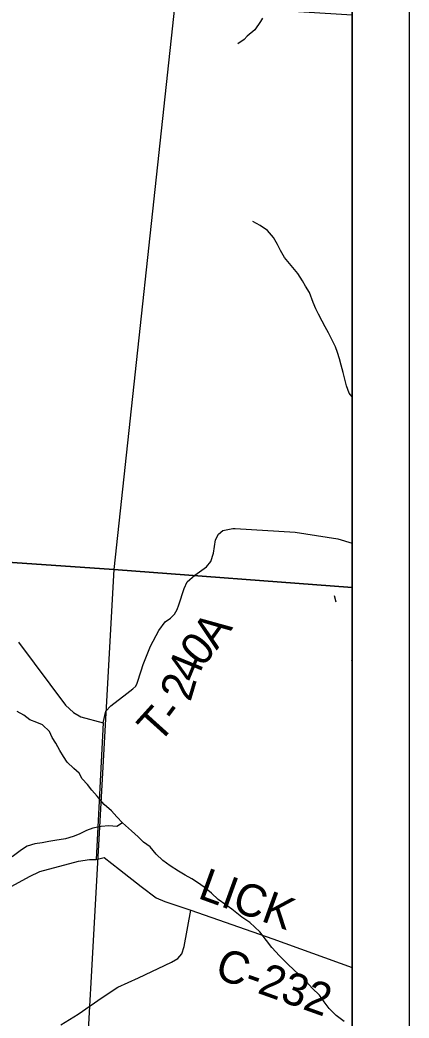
# Model space of a CAD drawing. Extents: x 0 to 34, y 0 to 22.
# Drawn here: x 8.316 to 9, y 15.475 to 17.231 of the extents above; entities that cross this region are included whole.
import ezdxf

# ---------------------------------------------------------------- set-up
doc = ezdxf.new("R2010")
doc.units = 0
for name, color, linetype in [('GM_X_Corporation', 7, 'Continuous'), ('GM_X_County_Road', 7, 'Continuous'), ('GM_X_County_Road_Text', 7, 'Continuous'), ('GM_X_Minor_River', 7, 'Continuous'), ('GM_X_Township_Road', 7, 'Continuous'), ('GM_X_Township_Road_Text', 7, 'Continuous'), ('SH_Data', 7, 'Continuous')]:
    doc.layers.add(name, color=color, linetype=linetype)

msp = doc.modelspace()

# ---------------------------------------------------------------- linework, layer by layer
at = {"layer": 'GM_X_Corporation'}
for p, q in [((8.9, 17.018), (8.9, 18.0245)), ((8.9, 14.1), (8.9, 18.0235)), ((8.9, 16.0103), (8.9, 17.018)), ((8.9, 15.0158), (8.9, 16.0103))]:
    msp.add_line(p, q, dxfattribs=at)
msp.add_lwpolyline([(8.9, 14.1), (8.9, 18.2459)], dxfattribs=at)
for points in [[(7.5885, 17.3345), (8.5882, 17.2585), (8.4813, 16.2644), (7.4964, 16.3324)], [(8.9, 16.2326), (8.9, 17.2392), (8.5882, 17.2585), (8.4813, 16.2644)], [(7.4964, 16.3324), (8.4813, 16.2644), (8.4262, 15.2749), (7.434, 15.3319)], [(8.9, 15.2382), (8.9, 16.2326), (8.4813, 16.2644), (8.4262, 15.2749)]]:
    msp.add_lwpolyline(points, close=True, dxfattribs=at)
at = {"layer": 'GM_X_County_Road'}
for points in [[(8.388, 15.4633), (8.4184, 15.4821), (8.4607, 15.5114), (8.4885, 15.5297), (8.5245, 15.5459), (8.5826, 15.5734), (8.5936, 15.5799), (8.6009, 15.5883), (8.6051, 15.6014), (8.6166, 15.6649)], [(8.6166, 15.6649), (8.7604, 15.6147), (8.9, 15.5645)]]:
    msp.add_lwpolyline(points, dxfattribs=at)
at = {"layer": 'GM_X_Minor_River'}
for p, q in [((8.8717, 16.2065), (8.8691, 16.2179)), ((8.9, 16.1042), (8.8991, 16.1045))]:
    msp.add_line(p, q, dxfattribs=at)
for points in [[(8.7426, 17.2339), (8.7392, 17.2283), (8.7288, 17.2131), (8.7155, 17.2022), (8.7101, 17.1965), (8.6991, 17.1886)], [(8.9, 16.5678), (8.895, 16.5745), (8.8902, 16.587), (8.8868, 16.6011), (8.8842, 16.6109), (8.8808, 16.6238), (8.8778, 16.6345), (8.8744, 16.6458), (8.8706, 16.6557), (8.8582, 16.6807), (8.8529, 16.691), (8.8473, 16.7012), (8.8409, 16.713), (8.836, 16.7229), (8.8315, 16.7339), (8.8251, 16.7513), (8.8183, 16.7623), (8.813, 16.7718), (8.8047, 16.7851), (8.7926, 16.7988), (8.7813, 16.8128), (8.7741, 16.8253), (8.7689, 16.836), (8.7617, 16.8481), (8.7515, 16.8606), (8.7383, 16.8694), (8.7254, 16.8762)], [(8.8858, 15.4691), (8.8718, 15.4801), (8.8594, 15.4923), (8.8511, 15.5037), (8.8428, 15.5155), (8.83, 15.5281), (8.8149, 15.5441), (8.7987, 15.5589), (8.7859, 15.5715), (8.7723, 15.5845), (8.7588, 15.5993), (8.7497, 15.6119), (8.7381, 15.6267), (8.72, 15.6431), (8.706, 15.653), (8.6886, 15.6671), (8.6781, 15.6744), (8.6648, 15.6839), (8.6528, 15.6949), (8.64, 15.7056), (8.6282, 15.7136), (8.6184, 15.7201), (8.6067, 15.7266), (8.595, 15.7335), (8.5803, 15.743), (8.5675, 15.7522), (8.5554, 15.7636), (8.5448, 15.7762), (8.5335, 15.7846), (8.5241, 15.7941), (8.512, 15.8044), (8.4966, 15.8188), (8.4864, 15.8295), (8.4773, 15.8398), (8.4641, 15.8508), (8.4517, 15.8653), (8.4423, 15.876), (8.4348, 15.8859), (8.4253, 15.8958), (8.4205, 15.906), (8.4107, 15.914), (8.399, 15.9254), (8.393, 15.9353), (8.3866, 15.946), (8.3794, 15.9585), (8.3731, 15.9688), (8.3682, 15.9794), (8.3557, 15.9909), (8.3459, 15.9951), (8.3338, 15.9997), (8.3232, 16.0081), (8.3112, 16.0146)], [(8.4966, 15.8188), (8.4863, 15.8124), (8.4723, 15.8136), (8.459, 15.8125), (8.4446, 15.8092), (8.4329, 15.8054), (8.4203, 15.799), (8.4097, 15.7945), (8.396, 15.7904), (8.3775, 15.7878), (8.3672, 15.7856), (8.3555, 15.7837), (8.3426, 15.7819), (8.3289, 15.7774), (8.3191, 15.7709), (8.3023, 15.7589)]]:
    msp.add_lwpolyline(points, dxfattribs=at)
at = {"layer": 'GM_X_Township_Road'}
for points in [[(8.5292, 16.086), (8.5328, 16.0972), (8.5454, 16.1294), (8.5602, 16.1571), (8.5713, 16.1719), (8.5808, 16.1787), (8.588, 16.1855), (8.5926, 16.1939), (8.5952, 16.2022), (8.6048, 16.231), (8.6101, 16.2424), (8.6238, 16.2542), (8.6439, 16.2689), (8.6515, 16.278), (8.6561, 16.2928), (8.66, 16.3163), (8.665, 16.3266), (8.6726, 16.3326), (8.6904, 16.3364), (8.6943, 16.3362)], [(8.6943, 16.3362), (8.7999, 16.33), (8.8749, 16.3184), (8.9, 16.3104)], [(8.3138, 16.1365), (8.369, 16.0623), (8.3965, 16.0258), (8.4101, 16.0128), (8.4234, 16.0052), (8.4626, 15.9947), (8.4504, 15.7542)], [(8.4626, 15.9947), (8.467, 16.0153), (8.4761, 16.0244), (8.5042, 16.046), (8.5145, 16.0543), (8.5198, 16.0589), (8.5225, 16.0645), (8.5292, 16.086)], [(8.2077, 15.685), (8.2352, 15.6888), (8.2619, 15.6983), (8.2877, 15.7014), (8.3018, 15.7073), (8.3332, 15.7244), (8.3511, 15.7333), (8.4189, 15.7512), (8.4387, 15.754), (8.4504, 15.7542)], [(8.4504, 15.7542), (8.4644, 15.7578), (8.4911, 15.7368), (8.5295, 15.7065), (8.5557, 15.6866), (8.5711, 15.6806), (8.6166, 15.6649)], [(8.6166, 15.6649), (8.7604, 15.6147), (8.9, 15.5645)]]:
    msp.add_lwpolyline(points, dxfattribs=at)
at = {"layer": 'SH_Data'}
for p, q in [((9, 21), (9, 14)), ((8.9, 20.9), (8.9, 14.1))]:
    msp.add_line(p, q, dxfattribs=at)

# ---------------------------------------------------------------- texts
at = {"layer": 'GM_X_County_Road_Text'}
for s, rotation, p in [('LICK', 340.0669, (8.6269, 15.6869)), ('C-232', 340.3462, (8.6561, 15.5471))]:
    msp.add_text(s, height=0.05682, rotation=rotation, dxfattribs=at).set_placement(p)
at = {"layer": 'GM_X_Township_Road_Text'}
for s, rotation, p in [('A', 54.2496, (8.6619, 16.1213)), ('0', 49.5641, (8.636, 16.0907)), ('4', 67.7212, (8.6252, 16.0624)), ('2', 73.4411, (8.6157, 16.0302)), ('T', 47.9682, (8.5599, 15.9562)), ('-', 52.9668, (8.5917, 15.9919))]:
    msp.add_text(s, height=0.0568, rotation=rotation, dxfattribs=at).set_placement(p)

doc.saveas('drawing.dxf')
